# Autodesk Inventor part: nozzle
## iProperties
Created: 2000-03
Part Number: nozzle
User Status: Reference File
Document SubType Name: Modeling
Designer: Peter Roberts
Manager: Dave Ford
Company: Autodesk Inc.
Control State: 0
Master: False
Checked Out: False
Shininess: 0.0
Length Units: 11269
Angle Units: 11279
Time Units: 11290
Mass Units: 11284
Length Display Precision: 1
Angle Display Precision: 2
Compacted: True
PropertySet Name: Model Information
Density: 0.0
Volumn: 0.0
Area: 0.0
Subject: Tutorial #2 part file
Author: Peter Roberts
